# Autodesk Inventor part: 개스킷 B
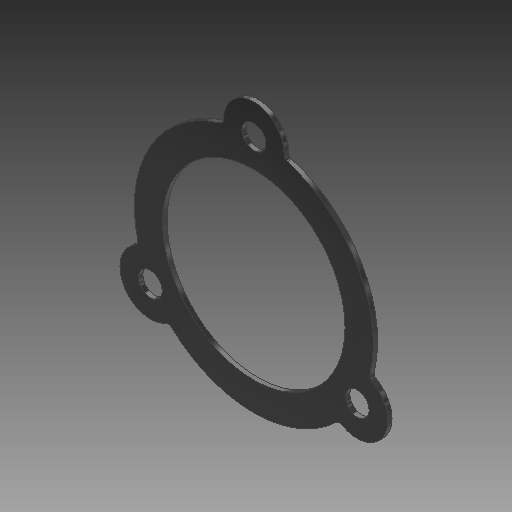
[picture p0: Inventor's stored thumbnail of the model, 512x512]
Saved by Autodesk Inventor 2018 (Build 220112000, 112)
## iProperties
Created: 2020-03
Part Number: 개스킷 B
Material: 고무
Document SubType Name: Modeling
Designer: mduedu
Density: 1 g/cm^3
Appearance: 고무 - 검은색 - 버전 1.1
Author: mduedu
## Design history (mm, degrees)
sketch "스케치1" dims "d1" = 55
  geometry: C1 r 21 at (0, 0); C2 r 7 at (0, 27.5); C3 r 7 at (-23.816, -13.75); C4 r 7 at (23.816, -13.75); 2 further points
  constraints: 4 centre point, 2 coincident, 2 vertical alignment, 9 other
  dimensions: "d0" = 42 diameter of C1; "d2" = 14 diameter of C2; "d5" = 360 deg dimension on point (0, 0) C2.centre (derived)
extrude "돌출1" new body sketch "스케치1" distance "d7" = 1; taper "d8" = 0 deg
extrude "돌출2" cut sketch "스케치1" extent not by distance; stored distance "d9" = 1; taper "d10" = 0 deg
fillet "모깎기1" dims "d11" = 1
sketch "스케치2"
  geometry: C1 r 21 at (0, 0) reference; A1 r 7 centre (0, 27.5) between (6.999, 27.373) and (-6.999, 27.373) reference; A2 r 27.5 centre (0, 0) between (26.718, -6.513) and (7.718, 26.395) reference; A3 r 1 centre (7.999, 27.355) between (6.999, 27.373) and (7.718, 26.395) reference; A4 r 7 centre (0, 27.5) between (6.999, 27.373) and (-6.999, 27.373) reference; A5 r 1 centre (-7.999, 27.355) between (-7.718, 26.395) and (-6.999, 27.373) reference; A6 r 27.5 centre (0, 0) between (-7.718, 26.395) and (-26.718, -6.513) reference; A7 r 1 centre (-27.689, -6.75) between (-27.205, -7.625) and (-26.718, -6.513) reference; A8 r 7 centre (-23.816, -13.75) between (-27.205, -7.625) and (-20.206, -19.748) reference; A9 r 1 centre (-19.69, -20.604) between (-19, -19.881) and (-20.206, -19.748) reference; A10 r 27.5 centre (0, 0) between (-19, -19.881) and (19, -19.881) reference; A11 r 1 centre (19.69, -20.604) between (20.206, -19.748) and (19, -19.881) reference; A12 r 7 centre (23.816, -13.75) between (20.206, -19.748) and (27.205, -7.625) reference; A13 r 1 centre (27.689, -6.75) between (26.718, -6.513) and (27.205, -7.625) reference; 4 further points
  constraints: 3 coincident
hole "구멍1" sketch "스케치2" at (0, 27.5), (23.816, -13.75), (-23.816, -13.75) diameter "d12" = 5.5; stored, may be unused: countersink angle "d16" = 90 deg, drill point angle "d18" = 118 deg; dims "d13" = 6, "d14" = 4, "d15" = 2, "d17" = 8
node "솔리드1"
node "투영된 루프1"
